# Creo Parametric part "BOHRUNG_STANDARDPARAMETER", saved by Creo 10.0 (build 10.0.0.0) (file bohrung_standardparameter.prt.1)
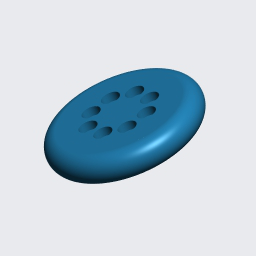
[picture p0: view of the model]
Materials in the file: S235JRG2

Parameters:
  BENENNUNG = "XXX"
  DATUM = "XX.XX.XX"
  ERSTELLER = "ARINDA"
  TEILETYP = "Fertigungsteil"
  PTC_MASTER_MATERIAL = "S235JRG2"
  SELECT_EN_NAME = "S235JRG2"
  SELECT_DIN_NAME = "RSt37-2"
  SELECT_DIN_NUMBER = "1.0038"
  SELECT_ASTM_NAME = "A 283 M Grade 2"
  MATERIAL_GROUP = "ME_ST_Baustahl"
  STANDARD_EN_DELIVERYSPEC = "DIN EN 10025"
  STANDARD_DIN_DELIVERYSPEC = "DIN 17100"

Other parameters: MASSE, BOHR_DURCHM

Created from: ARINDA-STARTTEIL.PRT

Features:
  1. coordinate system "CS0"
  2. datum plane "DTM1", "T_RECHTS_Y-Z"
  3. datum plane "DTM2", "T_OBEN_X-Z"
  4. datum plane "DTM3", "T_VORNE_X-Y"
  5. datum axis "T_X-ACHSE"
  6. datum axis "A_1"
  7. datum axis "A_2"
  8. extrusion "Profil 1"
  9. round "Rundung 1"
  10. pattern "Muster 1"
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
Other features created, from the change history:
  datum point "PNT0"
  hole "Bohrung 1"
  hole "Bohrung 1 [2]"
  hole "Bohrung 1 [3]"
  hole "Bohrung 1 [4]"
  hole "Bohrung 1 [5]"
  hole "Bohrung 1 [6]"
  hole "Bohrung 1 [7]"
  hole "Bohrung 1 [8]"

Other named items: T_BASIC, T_Y-ACHSE, T_Z-ACHSE

Layers: 00_STD-ACHSEN, 00_STD-EBENEN, 00_STD-KOORDSYS, 01_ACHSEN, 01_PUNKTE, VOLUMENGEOMETRIE

Notes: DRILL (  | 12.000 | 6.000 | HOLES

Surfaces: 10 plane, 8 cylinder, 2 torus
